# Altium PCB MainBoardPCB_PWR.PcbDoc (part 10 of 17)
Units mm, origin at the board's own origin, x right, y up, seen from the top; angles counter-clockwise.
Board outline 333.63 x 349.38 mm, 16 copper layers (L1, L2 (GND), L3 (Sign), L4 (GND), L5 (Sign), L6 (PWR/GND), L7(PWR/GND), L8 (PWR/GND), L9 (PWR/GND), L10 (PWR/GND), L11 (PWR/GND), L12 (Sign), L13 (GND), L14 (Sign), L15 (GND), L16), stack 2.503 mm thick; 2187 components, 1615 nets, 7987 pads, 1695 vias.
Unrouted connection lines stored in the file: 4757.
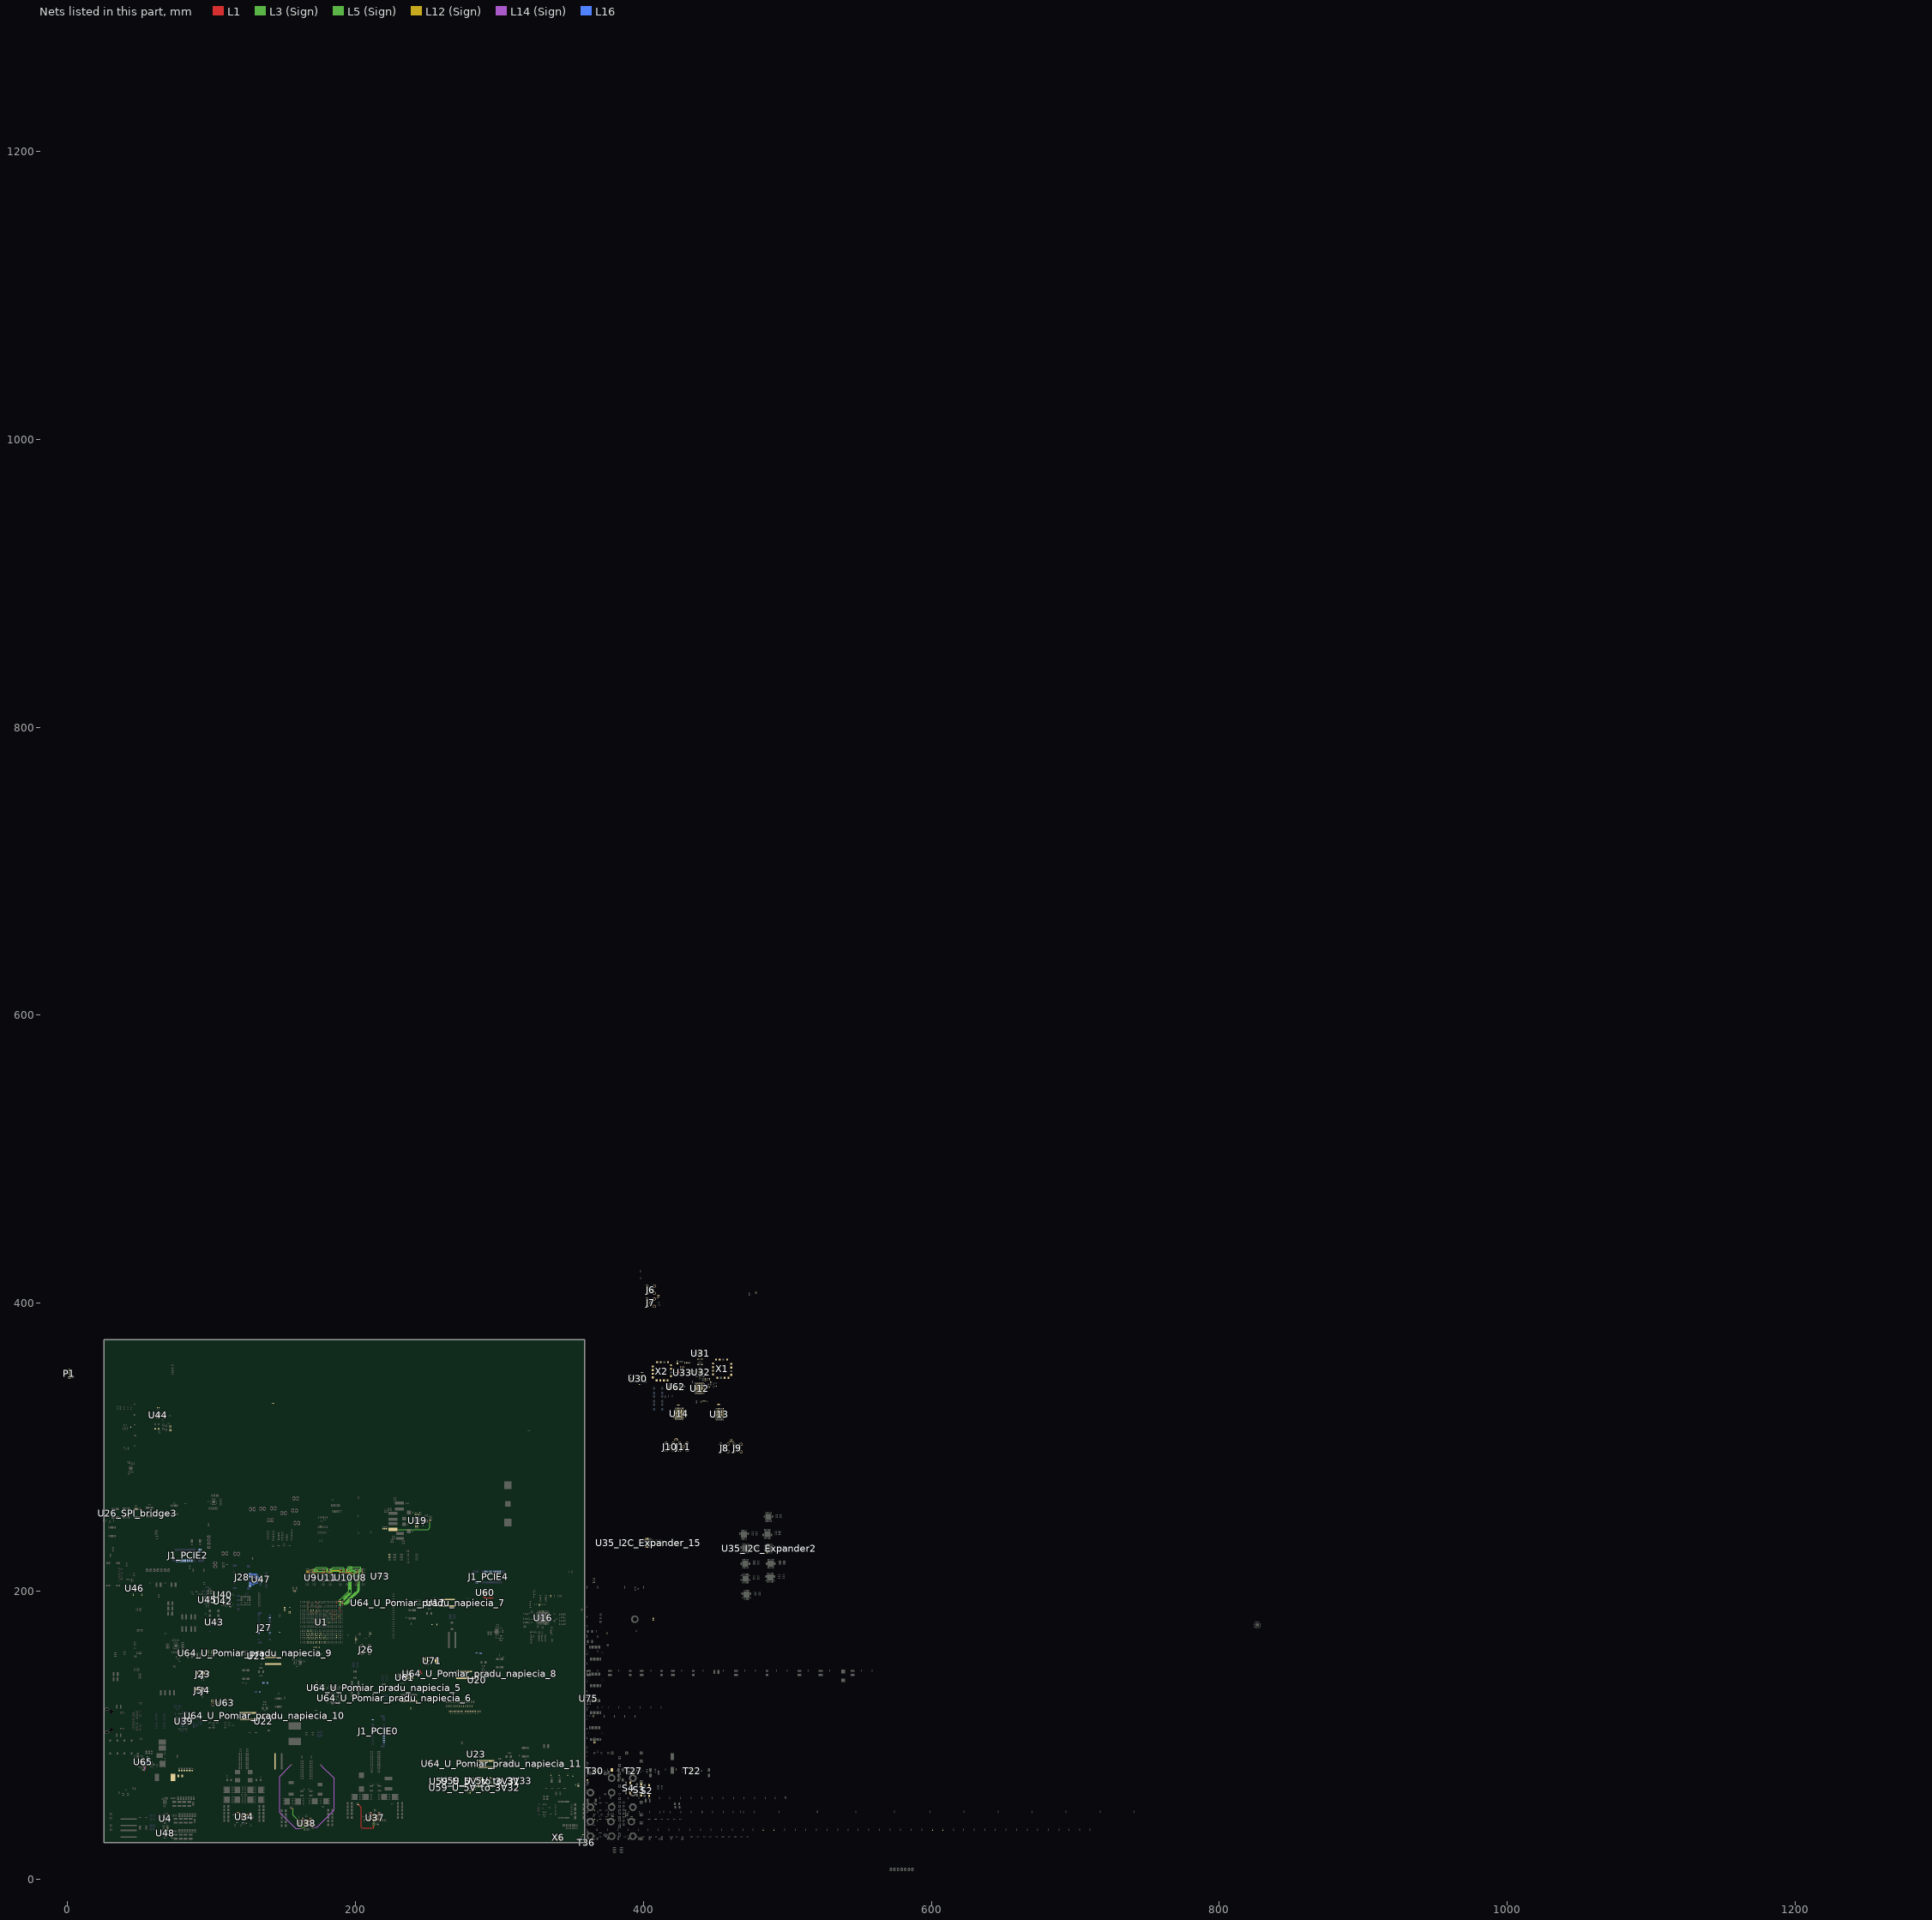
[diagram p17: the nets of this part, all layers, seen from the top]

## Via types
v1: diameter 0.5, hole 0.2, L1 to L16, 786 vias
v2: diameter 0.5/0.35/0.35/0.35/0.35/0.35/0.35/0.35/0.35/0.35/0.35/0.35/0.35/0.35/0.35/0.5 (per signal layer), hole 0.15, L1 to L16, tented both sides, 164 vias
v3: diameter 2.54, hole 1.02, L1 to L16, 152 vias
v4: diameter 0.5/0.35/0.35/0.35/0.35/0.35/0.35/0.35/0.35/0.35/0.35/0.35/0.35/0.35/0.35/0.5 (per signal layer), hole 0.2, L1 to L16, tented both sides, 100 vias
v5: diameter 0.45, hole 0.15, L1 to L16, 79 vias
v6: diameter 0.35/0/0.35 (per signal layer), hole 0.127, L1 to L3 (Sign), tented both sides, 78 vias
v7: diameter 0.45/0.45/0.45/0.45/0.45/0.45/0.45/0.45/0.45/0.45/0.45/0.45/0.45/0.45/0.45/0.45 (per signal layer), hole 0.15, L1 to L16, 65 vias
v8: diameter 0.4, hole 0.15, L1 to L16, 61 vias
v9: diameter 0.2, hole 0.1, L1 to L16, 35 vias
v10: diameter 0.5, hole 0.2, L1 to L16, tented both sides, 32 vias
v11: diameter 0.2/0/0.2 (per signal layer), hole 0.1, L1 to L3 (Sign), 28 vias
v12: diameter 0.4, hole 0.2, L1 to L16, 16 vias
v13: diameter 0.25, hole 0.2, L1 to L16, 16 vias
v14: diameter 0.3, hole 0.2, L1 to L16, 15 vias
v15: diameter 0.5/0.35/0.35/0.35/0.35/0.35/0.35/0.35/0.35/0.35/0.35/0.35/0.35/0.35/0.35/0.45 (per signal layer), hole 0.15, L1 to L16, tented both sides, 10 vias
v16: diameter 5, hole 3, L1 to L16, 9 vias
v17: diameter 0.2/0/0.2 (per signal layer), hole 0.1, L1 to L3 (Sign), tented both sides, 9 vias
v18: diameter 0.35/0/0.35 (per signal layer), hole 0.127, L1 to L3 (Sign), 7 vias
v19: diameter 0.35/0/0.35 (per signal layer), hole 0.127, L14 (Sign) to L16, tented both sides, 5 vias
v20: diameter 1.65, hole 1.65, L1 to L16, 4 vias
v21: diameter 1.15, hole 1.15, L1 to L16, 4 vias
v22: diameter 0.35, hole 0.127, L1 to L2 (GND), 2 vias
v23: diameter 0.4, hole 0.2, L1 to L16, tented both sides, 2 vias
v24: diameter 0.35, hole 0.127, L1 to L2 (GND), tented both sides, 2 vias
v25: diameter 0.508, hole 0.127, L1 to L2 (GND), 2 vias
v26: diameter 0.508, hole 0.127, L2 (GND) to L3 (Sign), 2 vias
v27: diameter 0.35, hole 0.127, L3 (Sign) to L6 (PWR/GND), tented both sides, 2 vias
v28: diameter 0.5, hole 0.2, L3 (Sign) to L6 (PWR/GND), tented both sides, 2 vias
v29: diameter 5.5, hole 3.5, L1 to L16, 1 vias
v30: diameter 0.45/0.45/0.45 (per signal layer), hole 0.15, L1 to L3 (Sign), 1 vias
v31: diameter 0.35/0.35/0.35 (per signal layer), hole 0.127, L1 to L3 (Sign), tented both sides, 1 vias
v32: diameter 0.45/0/0.45 (per signal layer), hole 0.15, L1 to L3 (Sign), tented both sides, 1 vias
v33: diameter 0.45/0/0.45 (per signal layer), hole 0.2, L14 (Sign) to L16, tented both sides, 1 vias
v34: diameter 0.35, hole 0.127, L2 (GND) to L3 (Sign), 1 vias

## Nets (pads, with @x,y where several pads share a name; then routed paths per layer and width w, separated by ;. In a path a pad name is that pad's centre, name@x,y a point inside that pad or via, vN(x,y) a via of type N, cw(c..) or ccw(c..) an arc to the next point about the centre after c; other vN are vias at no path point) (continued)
5V_RAIL: C515.2 C516.2 C563_U_5V_to_3V31.2 C563_U_5V_to_3V32.2 C563_U_5V_to_3V33.2 C564_U_5V_to_3V31.2 C564_U_5V_to_3V32.2 C564_U_5V_to_3V33.2 C574.2 C575.2 C720.2 C728.2 C733.2 D23.2 R315.2 R448_U_Pomiar_pradu_napiecia_6.2 R651.2 R656.2 T22.1 T27.2 T30.2 U40.1 U40.2 U40.3 U42.1 U42.2 U42.3 U45.21 U46.C3 U46.D3 U46.D4 U46.E3 U46.E4 U46.F3 U46.F4 U59_U_5V_to_3V31.1 U59_U_5V_to_3V31.2 U59_U_5V_to_3V32.1 U59_U_5V_to_3V32.2 U59_U_5V_to_3V33.1 U59_U_5V_to_3V33.2 U61.1 U61.2 U61.4 U61.5 U64_U_Pomiar_pradu_napiecia_6.8 U64_U_Pomiar_pradu_napiecia_6.9 U73.1 | length 54.5
  L14 (Sign) w0.254: v8(170.799,36.103) 173.242,36.103 185.2,48.06 ; v9(175.872,79.295) 185.204,69.963 185.204,48.06
12V_HiSpeed: C304.1 C305.1 C306.1 C307.1 C604.2 C714.2 FB34.1 L15.1 R448_U_Pomiar_pradu_napiecia_5.2 R626.2 U17.C3 U17.D3 U17.D4 U17.E3 U17.E4 U17.F3 U17.F4 U19.9 U19.11 U19.26 U19.28 U20.C3 U20.D3 U20.D4 U20.E3 U20.E4 U20.F3 U20.F4 U21.C3 U21.D3 U21.D4 U21.E3 U21.E4 U21.F3 U21.F4 U22.C3 U22.D3 U22.D4 U22.E3 U22.E4 U22.F3 U22.F4 U23.C3 U23.D3 U23.D4 U23.E3 U23.E4 U23.F3 U23.F4 U64_U_Pomiar_pradu_napiecia_5.8 U64_U_Pomiar_pradu_napiecia_5.9 U71.1 | length 58.1
  L1 w0.254: v8(161.537,35.058) R626.2@161.887,35.058 ; 245.476,144.878 245.476,143.28 245.982,142.773 245.982,142.723
  L14 (Sign) w0.254: v9(155.553,79.395) 147.38,71.222 147.38,46.175 158.497,35.058 v8(161.537,35.058)
12V_PCIE0: R448_U_Pomiar_pradu_napiecia_7.1 U17.C2 U17.D1 U17.D2 U17.E1 U17.E2 U17.F1 U17.F2 U64_U_Pomiar_pradu_napiecia_7.10
12V_PCIE0_CM: J1_PCIE0.60 J1_PCIE0.62 J1_PCIE0.64 J1_PCIE0.66 R448_U_Pomiar_pradu_napiecia_7.2 U64_U_Pomiar_pradu_napiecia_7.8 U64_U_Pomiar_pradu_napiecia_7.9
12V_PCIE1: R448_U_Pomiar_pradu_napiecia_8.1 U20.C2 U20.D1 U20.D2 U20.E1 U20.E2 U20.F1 U20.F2 U64_U_Pomiar_pradu_napiecia_8.10
12V_PCIE1_CM: R448_U_Pomiar_pradu_napiecia_8.2 U64_U_Pomiar_pradu_napiecia_8.8 U64_U_Pomiar_pradu_napiecia_8.9
12V_PCIE2: R448_U_Pomiar_pradu_napiecia_9.1 U21.C2 U21.D1 U21.D2 U21.E1 U21.E2 U21.F1 U21.F2 U64_U_Pomiar_pradu_napiecia_9.10
12V_PCIE2_CM: J1_PCIE2.60 J1_PCIE2.62 J1_PCIE2.64 J1_PCIE2.66 R448_U_Pomiar_pradu_napiecia_9.2 U64_U_Pomiar_pradu_napiecia_9.8 U64_U_Pomiar_pradu_napiecia_9.9
12V_PCIE3: R448_U_Pomiar_pradu_napiecia_10.1 U22.C2 U22.D1 U22.D2 U22.E1 U22.E2 U22.F1 U22.F2 U64_U_Pomiar_pradu_napiecia_10.10
12V_PCIE3_CM: R448_U_Pomiar_pradu_napiecia_10.2 U64_U_Pomiar_pradu_napiecia_10.8 U64_U_Pomiar_pradu_napiecia_10.9
12V_PCIE4: R448_U_Pomiar_pradu_napiecia_11.1 U23.C2 U23.D1 U23.D2 U23.E1 U23.E2 U23.F1 U23.F2 U64_U_Pomiar_pradu_napiecia_11.10
12V_PCIE4_CM: J1_PCIE4.60 J1_PCIE4.62 J1_PCIE4.64 J1_PCIE4.66 R448_U_Pomiar_pradu_napiecia_11.2 U64_U_Pomiar_pradu_napiecia_11.8 U64_U_Pomiar_pradu_napiecia_11.9
\I\N\T\: R709.2 U39.44
\M\R\: D11.1 D12.1 P5.1 R371.1 U44.13
ADP1741_3.6V: C308.2 C354.2 C355.2 C570.2 C603.2 L13.2 R113.2 U60.1 U60.2 U60.3 U60.15 U60.16 | length 31.4
  L1 w0.254: L13.2@225.965,242.859 229.313,242.859 229.431,242.741 v18(229.457,242.741) ; R113.2@251.788,249.011 251.788,248.318 251.811,248.295 v18(251.811,248.258)
  L3 (Sign) w0.254: v18(229.457,242.741) 250.449,242.741 251.811,244.104 v18(251.811,248.258)
ADP1741_EN: U35_I2C_Expander2.18 U60.4
ADP1741_PG: U35_I2C_Expander2.2 U60.5 | length 8.3
  L1 w0.254: U60.5@289.065,197.356 289.065,196.001 289.606,195.46 295.801,195.46
ADP_Vin_1: C395.2 R285.2 U37.3 | length 30.2
  L1 w0.254: R285.2@201.912,51.702 201.962,51.702 202.135,51.529 202.135,51.479 203.987,49.627 203.987,36.069 204.459,35.596 212.415,35.596 212.68,35.861 212.68,36.868 C395.2@212.81,36.998 v11(212.92,36.999) ; U37.3@212.795,40.359 212.795,39.955 v11(212.86,39.889)
  L3 (Sign) w0.254: v11(212.86,39.889) 212.92,39.83 v11(212.92,36.999)
ADP_Vin_2: C436.2 R303.2 U38.3 | length 19.4
  L1 w0.254: R303.2@155.628,49.178 v11(156.259,49.178) ; C436.2@160.318,38.813 v11(160.318,38.943) ; v11(165.283,36.265) U38.3@165.283,36.515
  L3 (Sign) w0.254: v11(156.259,49.178) 156.284,49.178 156.684,48.778 156.684,44.502 160.318,40.868 v11(160.318,38.943) 160.8,38.462 160.8,38.044 162.734,36.11 165.129,36.11 v11(165.283,36.265)
AGND: C45.1 C46.1 C55.1 C56.1 C57.1 C58.1 C59.1 C60.1 C61.1 C62.1 C65.1 C66.1 C68.1 C69.1 C71.1 C72.1 C73.1 C74.1 C84.1 C85.1 C86.1 C87.1 C94.1 C95.1 C97.1 C98.1 C111.1 C112.1 C113.1 C114.1 C115.1 C116.1 C117.1 C118.1 C119.1 C120.1 C121.1 C122.1 C123.1 C128.1 C129.1 C130.1 C131.1 C132.1 C133.1 C134.1 C135.1 C136.1 C137.1 C138.1 C139.1 C140.1 C149.1 C150.1 C151.1 C152.1 C153.1 C154.1 C155.1 C156.1 C157.1 C158.1 C159.1 C160.1 C161.1 C166.1 C167.1 C168.1 C169.1 C170.1 C171.1 C172.1 C173.1 C174.1 C175.1 C176.1 C177.1 C178.1 C181.1 C182.1 C183.1 C184.1 C185.1 C186.1 C187.1 C188.1 C189.1 C190.1 C191.1 C192.1 C193.1 C194.1 C195.1 C196.1 C197.1 C198.1 C199.1 C200.1 C201.1 C202.1 C203.1 C204.1 C205.1 C206.1 C322.1 C323.1 C324.1 C326.1 C327.1 C328.1 C329.1 C335.1 C336.1 C337.1 C338.1 C339.1 C340.1 C344.2 C563_U_5V_to_3V31.1 C563_U_5V_to_3V32.1 C563_U_5V_to_3V33.1 C564_U_5V_to_3V31.1 C564_U_5V_to_3V32.1 C564_U_5V_to_3V33.1 C565_U_5V_to_3V31.1 C565_U_5V_to_3V32.1 C565_U_5V_to_3V33.1 C566_U_5V_to_3V31.1 C566_U_5V_to_3V32.1 C566_U_5V_to_3V33.1 C567_U_5V_to_3V31.1 C567_U_5V_to_3V32.1 C567_U_5V_to_3V33.1 C568.1 C569.1 C570.1 C571.2 C580.1 C581.1 C582.1 C583.1 C584.1 C713.1 C714.1 FB35.2 J2.1 J2.3 J3.1 J3.3 J4.1 J4.3 J5.1 J5.3 J6.2 J6.3 J6.4 J6.5 J7.2 J7.3 J7.4 J7.5 J8.2 J8.3 J8.4 J8.5 J9.2 J9.3 J9.4 J9.5 J10.2 J10.3 J10.4 J10.5 J11.2 J11.3 J11.4 J11.5 J26.2 J26.3 J26.4 J26.5 R246.1 R247.1 R248.1 R249.2 R254.1 R255.1 R256.1 R258.2 R261.1 R262.1 R263.1 R264.1 R265.1 R291.2 R301.2 R387.1 R432_U_5V_to_3V31.1 R432_U_5V_to_3V32.1 R432_U_5V_to_3V33.1 R434.1 R444.1 R445.1 R482.2 R483.2 R487.1 R536.2 R537.1 R609.1 T36.2 U12.36 U12.41 U12.53 U13.36 U13.41 U13.53 U14.36 U14.41 U14.53 U31.1 U31.2 U31.17 U32.1 U32.17 U33.5 U33.6 U33.14 U33.17 U59_U_5V_to_3V31.4 U59_U_5V_to_3V31.9 U59_U_5V_to_3V32.4 U59_U_5V_to_3V32.9 U59_U_5V_to_3V33.4 U59_U_5V_to_3V33.9 U60.6 U60.17 U62.5 U62.8 U62.11 U71.2 X1.1 X1.3 X1.4 X1.5 X1.6 X1.7 X1.8 X1.9 X1.11 X1.12 X1.13 X1.15 X1.16 | length 10.2
  L1 w0.116: v4(182.44,184.44) 182.927,184.927 ; v10(183.44,182.44) 183.927,182.927 ; 184.44,180.44 184.927,180.927 ; v4(184.44,186.414) 184.927,185.927 ; v4(185.44,183.44) 185.927,183.927 ; v10(186.44,181.44) 186.927,181.927 ; v4(186.44,192.414) 186.927,191.927 ; v4(188.44,182.44) 188.927,182.927 ; 188.927,187.927 v4(189.414,188.414) ; v10(189.44,180.44) 189.927,180.927 ; 189.927,185.927 v4(190.414,186.414) ; 189.927,190.927 v4(190.414,190.44) ; 190.927,192.927 v4(191.414,193.414)
  L1 w0.254: U60.6@289.715,197.356 289.715,196.668 290.047,196.336 290.047,196.326 C571.2@290.07,196.303
  other v1: 282.254,63.034 283.254,63.034 282.254,64.034 283.254,64.034 282.497,67.484 283.497,67.484 290.431,67.809 291.431,67.809 282.497,68.484 283.497,68.484 290.431,68.809 291.431,68.809 289.49,198.481 290.59,198.481 289.49,199.582 290.59,199.582 450.58,320.088 451.68,320.088 452.78,320.088 453.88,320.088 454.98,320.088 422.513,320.338 423.613,320.338 424.713,320.338 425.813,320.338 426.913,320.338 450.58,321.188 451.68,321.188 452.78,321.188 453.88,321.188 454.98,321.188 422.513,321.438 423.613,321.438 424.713,321.438 425.813,321.438 426.913,321.438 450.58,322.288 451.68,322.288 452.78,322.288 453.88,322.288 454.98,322.288 422.513,322.538 423.613,322.538 424.713,322.538 425.813,322.538 426.913,322.538 450.58,323.388 451.68,323.388 452.78,323.388 453.88,323.388 454.98,323.388 422.513,323.638 423.613,323.638 424.713,323.638 425.813,323.638 426.913,323.638 450.58,324.488 451.68,324.488 452.78,324.488 453.88,324.488 454.98,324.488 422.513,324.738 423.613,324.738 424.713,324.738 425.813,324.738 426.913,324.738 450.58,325.588 451.68,325.588 452.78,325.588 453.88,325.588 454.98,325.588 422.513,325.838 423.613,325.838 424.713,325.838 425.813,325.838 426.913,325.838 436.668,338.092 437.768,338.092 438.868,338.092 439.968,338.092 441.068,338.092 436.668,339.192 437.768,339.192 438.868,339.192 439.968,339.192 441.068,339.192 436.668,340.292 437.768,340.292 438.868,340.292 439.968,340.292 441.068,340.292 421.949,341.08 422.711,341.08 436.668,341.392 437.768,341.392 438.868,341.392 439.968,341.392 441.068,341.392 421.949,341.842 422.711,341.842 436.668,342.492 437.768,342.492 438.868,342.492 439.968,342.492 441.068,342.492 421.949,342.604 422.711,342.604 436.668,343.592 437.768,343.592 438.868,343.592 439.968,343.592 441.068,343.592
  other v4: 168.927,182.927 178.927,182.927 180.927,183.927 167.927,184.927 168.927,184.927 169.927,184.927 170.927,184.927 171.927,184.927 172.927,184.927 177.927,184.927 167.927,185.927 173.927,185.927 179.927,185.927 166.927,186.927 167.927,186.927 169.927,186.927 171.927,186.927 173.927,186.927 176.927,186.927 166.927,187.927 173.927,187.927 166.927,188.927 168.927,188.927 170.927,188.927 172.927,188.927 173.927,188.927 175.927,188.927 166.927,189.927 167.927,189.927 169.927,189.927 173.927,189.927 177.927,189.927 166.927,190.927 167.927,190.927 169.927,190.927 171.927,190.927 173.927,190.927 166.927,191.927 168.927,191.927 170.927,191.927 172.927,191.927 173.927,191.927 176.927,191.927 166.927,192.927 168.927,192.927 170.927,192.927 172.927,192.927 173.927,192.927
  other v12: 426.527,351.311 427.477,351.311 426.527,352.261 427.477,352.261
AGND_1: C389.1 C393.1 C395.1 C398.1 C399.1 C639.1 C640.1 C641.1 C642.1 C643.1 C644.1 R290.1 R294.1 R300.1 U37.6 U37.33
  other v1: 212.945,41.059 214.145,41.059 211.995,42.009 212.945,42.009 214.145,42.009 215.095,42.009 211.995,43.209 212.945,43.209 214.145,43.209 215.095,43.209 212.945,44.159 214.145,44.159
  other v5: 211.905,36.998 215.795,37.716 212.295,38.101 214.259,39.727 207.935,41.139 219.162,41.194 206.788,41.314 209.061,41.359 218.07,41.359 220.17,41.34 208.941,42.36 217.945,42.359 205.776,43.462 208.951,45.299 218.055,45.314
AGND_2: C430.1 C434.1 C436.1 C439.1 C440.1 C548.1 C549.1 C647.1 C648.1 C650.1 C652.1 R312.1 R318.1 R627.1 U38.6 U38.33
  other v1: 165.433,37.215 166.633,37.215 164.483,38.165 165.433,38.165 166.633,38.165 167.583,38.165 164.483,39.365 165.433,39.365 166.633,39.365 167.583,39.365 165.433,40.315 166.633,40.315
  other v5: 167.448,34.037 170.674,35.175 162.014,36.005 171.666,37.79 160.268,37.9 170.624,37.89 161.469,38.015 170.624,38.803 161.453,39.015
Analog_In5: U1.AD14
Analog_In6: U1.AA14
Analog_In7: U1.AB14
ANGD: C345.1 C349.1 C351.1 C356.1 C357.1 C358.2 C634.1 C635.1 R273.1 U34.6 U34.33
  other v1: 124.277,37.96 121.487,38.325 122.127,41.606 123.327,41.606 118.596,41.923 127.919,42.524 121.177,42.556 122.127,42.556 123.327,42.556 124.277,42.556 121.177,43.756 122.127,43.756 123.327,43.756 124.277,43.756 127.934,44.139 117.646,44.404 116.442,44.623 122.127,44.706 123.327,44.706
B223_Rx0_N: J1_PCIE0.47 U1.W3
B223_Rx0_P: J1_PCIE0.49 U1.W4
B223_Rx1_N: J1_PCIE0.35 U1.V5
B223_Rx1_P: J1_PCIE0.37 U1.V6
B223_Rx2_N: U1.T5
B223_Rx2_P: U1.T6
B223_Rx3_N: U1.R3
B223_Rx3_P: U1.R4
B223_Tx0_to_C_N: C268.1 J1_PCIE0.41
B223_Tx0_to_C_P: C267.1 J1_PCIE0.43
B223_Tx0C_to_B_N: C268.2 U1.V1
B223_Tx0C_to_B_P: C267.2 U1.V2
B223_Tx1_to_C_N: C270.1 J1_PCIE0.29
B223_Tx1_to_C_P: C269.1 J1_PCIE0.31
B223_Tx1C_to_B_N: C270.2 U1.U3
B223_Tx1C_to_B_P: C269.2 U1.U4
B223_Tx2_to_C_N: C272.1
B223_Tx2_to_C_P: C271.1
B223_Tx2C_to_B_N: C272.2 U1.T1
B223_Tx2C_to_B_P: C271.2 U1.T2
B223_Tx3_to_C_N: C275.1
B223_Tx3_to_C_P: C274.1
B223_Tx3C_to_B_N: C275.2 U1.P1
B223_Tx3C_to_B_P: C274.2 U1.P2
B224_Rx0_N: J1_PCIE2.47 U1.P5
B224_Rx0_P: J1_PCIE2.49 U1.P6
B224_Rx1_N: J1_PCIE2.35 U1.M5
B224_Rx1_P: J1_PCIE2.37 U1.M6
B224_Rx2_N: U1.L3
B224_Rx2_P: U1.L4
B224_Rx3_N: U1.K5
B224_Rx3_P: U1.K6
B224_Tx0_to_C_N: C280.1 J1_PCIE2.41
B224_Tx0_to_C_P: C279.1 J1_PCIE2.43
B224_Tx0C_to_B_N: C280.2 U1.N3
B224_Tx0C_to_B_P: C279.2 U1.N4
B224_Tx1_to_C_N: C282.1 J1_PCIE2.29
B224_Tx1_to_C_P: C281.1 J1_PCIE2.31
B224_Tx1C_to_B_N: C282.2 U1.M1
B224_Tx1C_to_B_P: C281.2 U1.M2
B224_Tx2_to_C_N: C284.1
B224_Tx2_to_C_P: C283.1
B224_Tx2C_to_B_N: C284.2 U1.K1
B224_Tx2C_to_B_P: C283.2 U1.K2
B224_Tx3_to_C_N: C287.1
B224_Tx3_to_C_P: C286.1
B224_Tx3C_to_B_N: C287.2 U1.J3
B224_Tx3C_to_B_P: C286.2 U1.J4
B225_Rx0_N: J1_PCIE4.47 U1.H5
B225_Rx0_P: J1_PCIE4.49 U1.H6
B225_Rx1_N: J1_PCIE4.35 U1.G7
B225_Rx1_P: J1_PCIE4.37 U1.G8
B225_Rx2_N: J1_PCIE4.23 U1.F5
B225_Rx2_P: J1_PCIE4.25 U1.F6
B225_Rx3_N: J1_PCIE4.11 U1.E7
B225_Rx3_P: J1_PCIE4.13 U1.E8
B225_Tx0_to_C_N: C292.1 J1_PCIE4.41
B225_Tx0_to_C_P: C291.1 J1_PCIE4.43
B225_Tx0C_to_B_N: C292.2 U1.H1
B225_Tx0C_to_B_P: C291.2 U1.H2
B225_Tx1_to_C_N: C294.1 J1_PCIE4.29
B225_Tx1_to_C_P: C293.1 J1_PCIE4.31
B225_Tx1C_to_B_N: C294.2 U1.G3
B225_Tx1C_to_B_P: C293.2 U1.G4
B225_Tx2_to_C_N: C296.1 J1_PCIE4.19
B225_Tx2_to_C_P: C295.1 J1_PCIE4.17
B225_Tx2C_to_B_N: C296.2 U1.F1
B225_Tx2C_to_B_P: C295.2 U1.F2
B225_Tx3_to_C_N: C299.1 J1_PCIE4.7
B225_Tx3_to_C_P: C298.1 J1_PCIE4.5
B225_Tx3C_to_B_N: C299.2 U1.E3
B225_Tx3C_to_B_P: C298.2 U1.E4
B503_Ground: C531.2 C532.2 C533.2 C534.2 C535.1 C536.1 P5.2 R358.2 R359.2 R360.2 R361.2 R373.1 R720.2 S2.3 S2.4 S3.3 S3.4 S4.3 S4.4 U43.9 U43.10 U44.4 U44.5 U44.17 X6.2 | length 0.9
  L1 w0.2: C535.1@157.404,200.432 C536.1@158.344,200.432
  other v1: 62.4,321.691 63.5,321.691 62.4,322.791 63.5,322.791
  other v22: 157.874,200.432
  other v34: 157.874,200.432
Bank223_MGTREF0_C_N: C276.1 U1.R7
Bank223_MGTREF0_C_P: C273.1 U1.R8
Bank223_MGTREF1_C_N: C278.1 U1.N7
Bank223_MGTREF1_C_P: C277.1 U1.N8
Bank224_MGTREF0_C_N: C288.1 U1.L7
Bank224_MGTREF0_C_P: C285.1 U1.L8
Bank224_MGTREF1_C_N: C290.1 U1.J7
Bank224_MGTREF1_C_P: C289.1 U1.J8
Bank225_MGTREF0_C_N: C300.1 U1.H9
Bank225_MGTREF0_C_P: C297.1 U1.H10
Bank225_MGTREF1_C_N: C302.1 U1.F9
Bank225_MGTREF1_C_P: C301.1 U1.F10
Bank505_MGTRREF0_C_N: C526.2 R69.2 U1.M24
Bank505_MGTRREF0_C_P: C525.2 R69.1 U1.M23
Bank505_MGTRREF2_C_N: C528.2 R126.2 U1.K24
Bank505_MGTRREF2_C_P: C527.2 R126.1 U1.K23
Bank505_MGTRREF3_C_N: C530.2 R70.2 U1.H24
Bank505_MGTRREF3_C_P: C529.2 R70.1 U1.H23
Battery_PWR: P11.1 R679.2 R680.2 U48.2
  other v12: 68.417,32.112
BST1: C346.1 U34.25 | length 2.7
  L1 w0.254: C346.1@118.426,46.421 118.963,46.421 120.404,44.979 120.404,44.908 120.406,44.906 U34.25@120.477,44.906
BST1_1: C390.1 U37.25 | length 2.2
  L1 w0.254: C390.1@210.696,46.316 210.701,46.316 211.295,45.723 U37.25@211.295,44.359
BST1_2: C431.1 U38.25 | length 1.7
  L1 w0.254: C431.1@163.383,42.063 163.383,42.058 163.783,41.658 U38.25@163.783,40.515
BST2: C350.1 U34.16 | length 2.6
  L1 w0.254: U34.16@124.977,44.906 125.561,44.906 126.668,46.013 126.871,46.013 C350.1@127.014,46.156
BST2_1: C394.1 U37.16 | length 2.2
  L1 w0.254: U37.16@215.795,44.359 215.866,44.359 216.265,44.758 C394.1@216.265,46.316
BST2_2: C435.1 U38.16 | length 1.7
  L1 w0.254: U38.16@168.283,40.515 168.283,41.723 168.633,42.073 C435.1@168.633,42.078
CAN1_RxD: R798.1 U63.1
CAN1_TxD: R799.1 U63.4
CAN_H: P6.2 R446.2 R447.2 U63.7 U75.2
CAN_L: P6.1 R446.1 R447.1 U63.6 U75.1
CD_H: J28.9 R381.1 R782.1 U47.D3
Charge_CAP_KEY: R658.2
CLK_Fanout_In_N: U1.AF5
CLK_Fanout_In_P: U1.AF6
CLK_GTR_T1_N: C528.1
CLK_GTR_T1_P: C527.1
CLK_GTR_T2_N: C526.1
CLK_GTR_T2_P: C525.1
CLK_GTR_T3_N: C530.1
CLK_GTR_T3_P: C529.1
CLK_Hi_Rail1_N: R270.1 U12.33 U13.38
CLK_Hi_Rail1_P: R270.2 U12.34 U13.37
CLK_Hi_Rail1_SysRef_N: R534.1 U12.30 U13.48
CLK_Hi_Rail1_SysRef_P: R534.2 U12.31 U13.47
CLK_Hi_Rail2_N: R539.1 U12.6 U14.38
CLK_Hi_Rail2_P: R539.2 U12.7 U14.37
CLK_Hi_Rail2_SysRef_N: R535.1 U12.3 U14.48
CLK_Hi_Rail2_SysRef_P: R535.2 U12.4 U14.47
CLK_M_OSC_In: C333.1 R257.2 U33.2 | length 2.7
  L1 w0.116: C333.1@422.947,351.917 422.993,351.917 R257.2@423.951,351.917 424.963,351.917 425.082,352.036 U33.2@425.602,352.036
CLK_NVME_Conn_N: J27.53 U14.13
CLK_NVME_Conn_P: J27.55 U14.12
CLK_Q223_T1_N: C276.2
CLK_Q223_T1_P: C273.2
CLK_Q224_T1_N: C288.2
CLK_Q224_T1_P: C285.2
CLK_Q225_T1_N: C300.2
CLK_Q225_T1_P: C297.2
CLK_Q226_T1_N: U1.B9
CLK_Q226_T1_P: U1.B10
CLK_SMA0_C_N: C48.2 J6.1
CLK_SMA0_C_P: C47.2 J7.1
CLK_SMA0_N: C48.1 R78.1 U12.9
CLK_SMA0_P: C47.1 R78.2 U12.10
CLK_SMA1_C_N: C50.2 J8.1
CLK_SMA1_C_P: C49.2 J9.1
CLK_SMA1_N: C50.1 R79.1 U13.3
CLK_SMA1_P: C49.1 R79.2 U13.4
CLK_SMA2_C_N: C52.2 J10.1
CLK_SMA2_C_P: C51.2 J11.1
CLK_SMA2_N: C52.1 R80.1 U14.34
CLK_SMA2_P: C51.1 R80.2 U14.33
CLKREF_R: R375.1 X6.3
CLKREQ: J27.52
CMD_SD: J28.3 U47.D4 | length 8
  L14 (Sign) w0.098: v33(129.438,209.982) 130.867,208.553 132.556,208.553 132.956,208.153 133.441,208.153 v19(133.841,207.753)
  L16 w0.098: J28.3@126.749,209.981 v33(129.438,209.982)
COMP1_1: C642.2 R624.2 U37.30 | length 2.7
  L1 w0.254: R624.2@209.801,40.359 209.821,40.379 209.821,41.339 C642.2@209.841,41.359 209.846,41.359 210.346,41.859 U37.30@211.295,41.859
COMP1_2: C548.2 R687.2 U38.30 | length 2.5
  L1 w0.254: R687.2@162.228,37.015 162.238,37.025 162.238,38.005 C548.2@162.249,38.015 U38.30@163.783,38.015
COMP2_1: C641.2 R623.2 U37.11 | length 2.6
  L1 w0.254: U37.11@215.795,41.859 216.66,41.859 217.16,41.359 C641.2@217.165,41.359 217.185,41.339 217.185,40.324 R623.2@217.205,40.305
COMP2_2: C650.2 R631.2 U38.11 | length 2.4
  L1 w0.254: U38.11@168.283,38.015 168.933,38.015 169.058,37.89 C650.2@169.734,37.89 169.754,37.87 169.754,37.02 R631.2@169.774,37
CSN: C694.2 C695.2 C696.2 C697.2 C698.2 C699.2 C700.2 R17.2 R140.2 R150.2 R666.2 U4.2 U65.10 | length 12.3
  L1 w0.254: R150.2@52.782,75.895 53.425,75.895 54.172,76.642 v9(54.172,78.202) 53.355,79.019 53.332,79.042 U65.10@53.332,79.367 ; R17.2@69.643,44.693 69.686,44.65 v5(70.536,44.65)
  L16 w0.254: v9(54.172,78.202) 54.172,80.097 56.068,81.993 v9@56.068,84.026
  other v9: 56.025,84.026
  other v12: 68.21,42.35
CSP: L22.2 R666.1 U65.9 | length 4.5
  L1 w0.254: U65.9@52.832,79.367 52.832,78.847 v9(53.572,78.107)
  L16 w0.254: v9(53.572,75.202) v9(53.572,78.107)
CSU: P1.2 R783.1
CSU_Neg: P1.3 R109.2
CSU_Pos: P1.1 R106.2
D_05028_G0: R540.2 U1.AA15 U16.45
D_05028_G0_1: R540.1 U35_I2C_Expander_15.2
D_05028_G3: U16.40 U35_I2C_Expander_15.18
D_05028_G4: U16.41 U35_I2C_Expander_15.3
D_05028_G5: U16.12 U35_I2C_Expander_15.22
D_05028_G6: U16.13 U35_I2C_Expander_15.19
D_05028_S0: U16.55 U35_I2C_Expander_15.21
D_05028_S1: U16.56 U35_I2C_Expander_15.20
DAC1220_Vref: C320.2 R608.1 R609.2 U30.12
DAC_AGND: U30.4 U30.13 X2.1 X2.3 X2.4 X2.5 X2.6 X2.7 X2.8 X2.9 X2.11 X2.12 X2.13 X2.15 X2.16
DAC_OUT: C321.2 U30.11 X2.2
DAC_SPI_CLK: U26_SPI_bridge3.14 U30.16
DAC_SPI_MOSI: R481.1 U26_SPI_bridge3.12 U30.15
DAS/DSS#: J27.10
DATA0_SD: J28.7 U47.D5 | length 8
  L16 w0.098: J28.7@126.749,205.581 126.98,205.812 131.593,205.812 131.978,206.197 131.978,206.896 132.836,207.753 U47.D5@133.439,207.753
DATA1_SD: J28.8 U47.E5 | length 8.3
  L16 w0.098: J28.8@126.749,204.481 129.361,204.481 130.48,205.6 131.762,205.6 132.309,206.146 132.309,206.794 132.868,207.353 U47.E5@133.439,207.353
DATA2_SD: J28.1 U47.A5 | length 8.6
  L16 w0.098: J28.1@126.749,212.181 131.141,212.181 131.886,211.436 131.886,210.506 U47.A5@133.439,208.953
DATA3_SD: J28.2 R383.1 U47.B5 | length 8
  L16 w0.098: J28.2@126.749,211.081 126.756,211.074 R383.1@130.487,211.074 130.487,210.546 131.356,209.677 132.067,209.677 133.191,208.553 U47.B5@133.439,208.553
Data_2_RX_PCIE0_N: J1_PCIE0.23
Data_2_RX_PCIE0_P: J1_PCIE0.25
Data_2_RX_PCIE1_N: 
Data_2_RX_PCIE1_P: 
Data_2_RX_PCIE2_N: J1_PCIE2.23
Data_2_RX_PCIE2_P: J1_PCIE2.25
Data_2_RX_PCIE3_N: 
Data_2_RX_PCIE3_P: 
Data_2_TX_PCIE0_N: J1_PCIE0.19
Data_2_TX_PCIE0_P: J1_PCIE0.17
Data_2_TX_PCIE1_N: 
Data_2_TX_PCIE1_P: 
Data_2_TX_PCIE2_N: J1_PCIE2.19
Data_2_TX_PCIE2_P: J1_PCIE2.17
Data_2_TX_PCIE3_N: 
Data_2_TX_PCIE3_P: 
Data_3_RX_PCIE0_N: J1_PCIE0.11
Data_3_RX_PCIE0_P: J1_PCIE0.13
Data_3_RX_PCIE1_N: 
Data_3_RX_PCIE1_P: 
Data_3_RX_PCIE2_N: J1_PCIE2.11
Data_3_RX_PCIE2_P: J1_PCIE2.13
Data_3_RX_PCIE3_N: 
Data_3_RX_PCIE3_P: 
Data_3_TX_PCIE0_N: J1_PCIE0.7
Data_3_TX_PCIE0_P: J1_PCIE0.5
Data_3_TX_PCIE1_N: 
Data_3_TX_PCIE1_P: 
Data_3_TX_PCIE2_N: J1_PCIE2.7
Data_3_TX_PCIE2_P: J1_PCIE2.5
Data_3_TX_PCIE3_N: 
Data_3_TX_PCIE3_P: 
DDR4_A0: R31.1 U1.AH30 U8.P3 U9.P3 U10.P3 U11.P3 | length 91.4
  L1 w0.116: v2(170.002,214.252) U9.P3@170.406,213.848 ; v2(181.463,214.252) U11.P3@181.866,213.848 ; U1.AH30@188.927,192.927 v6(189.414,193.414) ; v1(192.923,214.252) U10.P3@193.327,213.848 ; v15(204.356,214.248) 204.388,214.248 U8.P3@204.787,213.848
  L5 (Sign) w0.092: v2(170.002,214.252) 170.533,214.252 170.95,214.668 171.801,214.668 172.524,215.392 179.954,215.392 181.095,214.252 v2(181.463,214.252) 182.058,214.252 182.475,214.668 183.261,214.668 183.985,215.392 191.415,215.392 192.555,214.252 v1(192.923,214.252) 193.454,214.252 193.871,214.668 194.721,214.668 195.445,215.392 195.58,215.392 ccw(c195.58,215.482) 195.669,215.482 195.669,215.832 cw(c195.759,215.832) 195.759,215.921 196.027,215.921 cw(c196.027,215.832) 196.117,215.832 196.117,215.392 196.117,215.287 ccw(c196.207,215.287) 196.207,215.198 196.475,215.198 ccw(c196.475,215.287) 196.565,215.287 196.565,215.392 196.565,215.832 cw(c196.654,215.832) 196.654,215.921 196.923,215.921 cw(c196.923,215.832) 197.013,215.832 197.013,215.392 197.013,215.287 ccw(c197.102,215.287) 197.102,215.198 197.371,215.198 ccw(c197.371,215.287) 197.46,215.287 197.46,215.392 197.46,215.832 cw(c197.55,215.832) 197.55,215.921 197.819,215.921 cw(c197.819,215.832) 197.908,215.832 197.908,215.392 197.908,215.287 ccw(c197.998,215.287) 197.998,215.198 198.266,215.198 ccw(c198.266,215.287) 198.356,215.287 198.356,215.302 cw(c198.446,215.302) 198.446,215.392 202.875,215.392 202.97,215.297 ccw(c203.034,215.36) 203.097,215.297 203.098,215.298 cw(c203.161,215.235) 203.225,215.298 203.415,215.108 cw(c203.351,215.045) 203.415,214.982 203.35,214.917 203.286,214.852 ccw(c203.349,214.789) 203.286,214.726 203.476,214.536 ccw(c203.539,214.599) 203.602,214.536 203.604,214.537 cw(c203.667,214.474) 203.73,214.537 203.946,214.322 204.02,214.248 v15(204.356,214.248) v15@204.392,214.248
  L3 (Sign) w0.092: v6(189.414,193.414) 189.575,193.575 189.949,193.575 190.04,193.484 190.04,193.233 190.309,192.965 190.309,192.823 190.037,192.552 189.76,192.552 189.564,192.748 189.294,192.748 189.093,192.547 189.093,192.269 189.347,192.015 189.347,191.998 189.57,191.775 189.57,191.481 189.27,191.181 189.27,190.998 189.268,190.997 189.268,190.92 189.267,190.918 189.267,190.721 189.093,190.547 189.093,190.281 189.281,190.093 189.618,190.093 189.821,190.297 189.821,190.534 190.169,190.881 190.729,190.881 191.365,191.517 193.257,191.517 202.603,200.863 202.603,200.962 ccw(c202.504,200.962) 202.504,201.062 201.92,201.062 cw(c201.92,201.161) 201.82,201.161 201.82,201.359 cw(c201.92,201.359) 201.92,201.459 202.603,201.459 202.657,201.459 ccw(c202.657,201.558) 202.756,201.558 202.756,201.756 ccw(c202.657,201.756) 202.657,201.856 202.603,201.856 201.92,201.856 cw(c201.92,201.955) 201.82,201.955 201.82,202.153 cw(c201.92,202.153) 201.92,202.253 202.603,202.253 202.657,202.253 ccw(c202.657,202.352) 202.756,202.352 202.756,202.55 ccw(c202.657,202.55) 202.657,202.65 202.603,202.65 202.467,202.65 cw(c202.467,202.749) 202.367,202.749 202.367,202.947 cw(c202.467,202.947) 202.467,203.047 202.603,203.047 202.657,203.047 ccw(c202.657,203.146) 202.756,203.146 202.756,203.344 ccw(c202.657,203.344) 202.657,203.444 202.603,203.444 202.465,203.444 cw(c202.465,203.543) 202.366,203.543 202.366,203.741 cw(c202.465,203.741) 202.465,203.841 202.603,203.841 202.657,203.841 ccw(c202.657,203.94) 202.756,203.94 202.756,204.138 ccw(c202.657,204.138) 202.657,204.238 202.603,204.238 201.92,204.238 cw(c201.92,204.337) 201.82,204.337 201.82,204.535 cw(c201.92,204.535) 201.92,204.635 202.603,204.635 202.657,204.635 ccw(c202.657,204.734) 202.756,204.734 202.756,204.932 ccw(c202.657,204.932) 202.657,205.032 202.603,205.032 202.461,205.032 cw(c202.461,205.131) 202.361,205.131 202.361,205.329 cw(c202.461,205.329) 202.461,205.429 202.603,205.429 202.657,205.429 ccw(c202.657,205.528) 202.756,205.528 202.756,205.726 ccw(c202.657,205.726) 202.657,205.826 202.673,205.826 cw(c202.673,205.895) 202.603,205.895 202.603,207.01 202.603,211.273 202.971,211.642 202.971,214.678 203.421,215.128 203.926,215.128 204.063,214.992 204.063,214.918 204.064,214.916 204.064,214.82 204.391,214.493 v15@204.391,214.252
DDR4_A1: R33.1 U1.AG30 U8.P4 U9.P4 U10.P4 U11.P4 | length 91.1
  L1 w0.116: U9.P4@167.206,213.848 167.602,214.245 v2(167.605,214.245) ; U11.P4@178.666,213.848 179.063,214.245 v2(179.065,214.245) ; U1.AG30@187.927,192.927 v6(188.414,193.414) ; U10.P4@190.127,213.848 190.523,214.245 v2(190.526,214.245) v2@190.484,214.203 ; v15(201.176,214.244) U8.P4@201.58,213.841
  L12 (Sign) w0.092: 165.856,214.245 166.253,213.848 166.886,213.848 167.241,214.203 167.563,214.203 v2(167.605,214.245) v2@167.841,214.245 ; v2@167.602,214.245 v2@167.841,214.245 ; v2@179.063,214.245 180.018,214.245 ; v15(201.176,214.244) 200.909,214.244 200.589,213.924 200,213.924 199.457,213.924 cw(c199.403,213.924) 199.403,213.869 199.063,213.869 cw(c199.063,213.924) 199.009,213.924 199.009,214.488 ccw(c198.919,214.488) 198.919,214.578 198.651,214.578 ccw(c198.651,214.488) 198.561,214.488 198.561,213.924 cw(c198.507,213.924) 198.507,213.869 198.167,213.869 cw(c198.167,213.924) 198.113,213.924 198.113,214.488 ccw(c198.024,214.488) 198.024,214.578 197.755,214.578 ccw(c197.755,214.488) 197.665,214.488 197.665,214.013 cw(c197.576,214.013) 197.576,213.924 197.442,213.924 196.362,213.924 195.638,214.648 194.551,214.648 194.417,214.648 ccw(c194.417,214.558) 194.327,214.558 194.327,214.529 cw(c194.238,214.529) 194.238,214.44 193.969,214.44 cw(c193.969,214.529) 193.88,214.529 193.88,214.558 ccw(c193.79,214.558) 193.79,214.648 193.332,214.648 191.166,214.648 190.762,214.245 v2(190.526,214.245) 190.484,214.203 190.162,214.203 189.865,213.906 189.116,213.906 188.468,214.554 183.334,214.554 183.245,214.643 180.416,214.643 180.018,214.245 ; v2@167.841,214.245 168.245,214.648 173.172,214.648 173.896,213.924 178.744,213.924 v2(179.065,214.245) 180.018,214.245
  L3 (Sign) w0.092: v6(188.414,193.414) 189.081,194.081 189.498,194.081 195.498,200.082 195.498,200.52 195.498,200.773 ccw(c195.399,200.773) 195.399,200.873 195.067,200.873 cw(c195.067,200.972) 194.968,200.972 194.968,201.17 cw(c195.067,201.17) 195.067,201.27 195.498,201.27 196.385,201.27 ccw(c196.385,201.369) 196.484,201.369 196.484,201.567 ccw(c196.385,201.567) 196.385,201.667 195.498,201.667 195.067,201.667 cw(c195.067,201.766) 194.968,201.766 194.968,201.964 cw(c195.067,201.964) 195.067,202.064 195.498,202.064 196.385,202.064 ccw(c196.385,202.163) 196.484,202.163 196.484,202.361 ccw(c196.385,202.361) 196.385,202.461 195.498,202.461 195.067,202.461 cw(c195.067,202.56) 194.968,202.56 194.968,202.758 cw(c195.067,202.758) 195.067,202.858 195.498,202.858 196.385,202.858 ccw(c196.385,202.957) 196.484,202.957 196.484,203.155 ccw(c196.385,203.155) 196.385,203.255 195.498,203.255 195.067,203.255 cw(c195.067,203.354) 194.968,203.354 194.968,203.552 cw(c195.067,203.552) 195.067,203.652 195.498,203.652 196.385,203.652 ccw(c196.385,203.751) 196.484,203.751 196.484,203.949 ccw(c196.385,203.949) 196.385,204.049 195.498,204.049 195.067,204.049 cw(c195.067,204.148) 194.968,204.148 194.968,204.346 cw(c195.067,204.346) 195.067,204.446 195.498,204.446 196.385,204.446 ccw(c196.385,204.545) 196.484,204.545 196.484,204.743 ccw(c196.385,204.743) 196.385,204.843 195.498,204.843 195.067,204.843 cw(c195.067,204.942) 194.968,204.942 194.968,205.14 cw(c195.067,205.14) 195.067,205.24 195.498,205.24 196.385,205.24 ccw(c196.385,205.339) 196.484,205.339 196.484,205.537 ccw(c196.385,205.537) 196.385,205.637 195.498,205.637 195.087,205.637 cw(c195.087,205.736) 194.988,205.736 194.988,205.934 cw(c195.087,205.934) 195.087,206.034 195.498,206.034 196.385,206.034 ccw(c196.385,206.133) 196.484,206.133 196.484,206.331 ccw(c196.385,206.331) 196.385,206.431 195.598,206.431 cw(c195.598,206.53) 195.498,206.53 195.498,206.629 195.498,206.868 196.136,207.505 196.136,209.821 200.132,213.817 200.477,213.817 200.619,213.958 200.623,213.958 200.909,214.244 v15(201.176,214.244)
DDR4_A2: R35.1 U1.AK29 U8.R3 U9.R3 U10.R3 U11.R3 | length 91.2
  L1 w0.116: v2(170.002,215.052) U9.R3@170.406,214.648 ; v2(181.463,215.052) U11.R3@181.866,214.648 ; v6(190.44,191.44) U1.AK29@190.927,191.927 ; v2(192.923,215.052) U10.R3@193.327,214.648 ; v15(204.384,215.052) U8.R3@204.787,214.648
  L5 (Sign) w0.092: v2(170.002,215.052) 170.431,215.052 170.835,215.456 171.742,215.456 172.793,216.507 179.627,216.507 181.082,215.052 v2(181.463,215.052) 181.963,215.052 182.367,215.456 183.202,215.456 184.253,216.507 191.087,216.507 192.542,215.052 v2(192.923,215.052) 193.352,215.052 193.756,215.456 194.663,215.456 194.907,215.7 194.907,216.865 194.983,216.941 195.021,216.941 195.156,216.941 ccw(c195.156,217.031) 195.245,217.031 195.245,217.132 cw(c195.335,217.132) 195.335,217.221 195.603,217.221 cw(c195.603,217.132) 195.693,217.132 195.693,216.941 195.693,216.908 ccw(c195.782,216.908) 195.782,216.818 196.051,216.818 ccw(c196.051,216.908) 196.141,216.908 196.141,216.941 196.141,217.132 cw(c196.23,217.132) 196.23,217.221 196.499,217.221 cw(c196.499,217.132) 196.588,217.132 196.588,216.941 196.588,216.751 ccw(c196.678,216.751) 196.678,216.662 196.947,216.662 ccw(c196.947,216.751) 197.036,216.751 197.036,216.941 197.036,217.132 cw(c197.126,217.132) 197.126,217.221 197.395,217.221 cw(c197.395,217.132) 197.484,217.132 197.484,216.941 197.484,216.751 ccw(c197.574,216.751) 197.574,216.662 197.842,216.662 ccw(c197.842,216.751) 197.932,216.751 197.932,216.852 cw(c198.021,216.852) 198.021,216.941 198.133,216.941 203.657,216.941 203.76,216.838 203.76,215.677 204.384,215.053 v15(204.384,215.052)
  L3 (Sign) w0.092: v6(190.44,191.44) 190.709,191.709 192.993,191.709 193.063,191.78 ccw(c192.993,191.85) 193.063,191.92 192.844,192.139 cw(c192.914,192.209) 192.844,192.279 192.984,192.42 cw(c193.054,192.35) 193.124,192.42 193.414,192.13 193.429,192.115 ccw(c193.499,192.186) 193.569,192.115 193.709,192.256 ccw(c193.639,192.326) 193.709,192.396 193.694,192.411 193.406,192.7 cw(c193.476,192.77) 193.406,192.84 193.546,192.981 cw(c193.616,192.91) 193.686,192.981 193.975,192.692 193.99,192.677 ccw(c194.06,192.747) 194.131,192.677 194.271,192.817 ccw(c194.201,192.887) 194.271,192.958 194.256,192.973 193.968,193.261 cw(c194.038,193.331) 193.968,193.401 194.108,193.541 cw(c194.178,193.471) 194.248,193.541 194.537,193.253 194.552,193.238 ccw(c194.622,193.308) 194.692,193.238 194.832,193.379 ccw(c194.762,193.449) 194.832,193.519 194.817,193.534 194.53,193.822 cw(c194.6,193.892) 194.53,193.962 194.67,194.102 cw(c194.74,194.032) 194.81,194.102 195.098,193.815 195.113,193.8 ccw(c195.183,193.87) 195.253,193.8 195.394,193.94 ccw(c195.324,194.01) 195.394,194.08 195.379,194.096 195.092,194.383 cw(c195.162,194.453) 195.092,194.523 195.232,194.663 cw(c195.302,194.593) 195.372,194.663 195.659,194.376 195.675,194.361 ccw(c195.745,194.431) 195.815,194.361 195.955,194.502 ccw(c195.885,194.572) 195.955,194.642 195.94,194.657 195.654,194.943 cw(c195.724,195.014) 195.654,195.084 195.794,195.224 cw(c195.864,195.154) 195.934,195.224 196.221,194.938 196.236,194.923 ccw(c196.306,194.993) 196.376,194.923 196.517,195.063 ccw(c196.446,195.133) 196.517,195.203 196.502,195.218 196.216,195.504 cw(c196.286,195.574) 196.216,195.645 196.356,195.785 cw(c196.426,195.715) 196.496,195.785 196.782,195.499 196.797,195.484 ccw(c196.868,195.554) 196.938,195.484 197.078,195.624 ccw(c197.008,195.695) 197.078,195.765 197.063,195.78 196.778,196.065 cw(c196.848,196.135) 196.778,196.206 196.918,196.346 cw(c196.988,196.276) 197.058,196.346 197.344,196.061 197.359,196.045 ccw(c197.429,196.116) 197.499,196.045 197.64,196.186 ccw(c197.569,196.256) 197.64,196.326 197.624,196.341 197.34,196.626 cw(c197.41,196.696) 197.34,196.766 197.48,196.907 cw(c197.55,196.837) 197.62,196.907 197.905,196.622 197.92,196.607 ccw(c197.99,196.677) 198.061,196.607 198.201,196.747 ccw(c198.131,196.817) 198.201,196.888 198.186,196.903 197.902,197.187 cw(c197.972,197.257) 197.902,197.327 198.042,197.468 cw(c198.112,197.397) 198.182,197.468 198.467,197.183 198.482,197.168 ccw(c198.552,197.239) 198.622,197.168 198.762,197.309 ccw(c198.692,197.379) 198.762,197.449 198.747,197.464 198.464,197.748 cw(c198.534,197.818) 198.464,197.888 198.604,198.029 cw(c198.674,197.958) 198.744,198.029 199.028,197.745 199.043,197.73 ccw(c199.113,197.8) 199.184,197.73 199.324,197.87 ccw(c199.254,197.94) 199.324,198.011 199.309,198.026 199.026,198.309 cw(c199.096,198.379) 199.026,198.449 199.166,198.589 cw(c199.236,198.519) 199.306,198.589 199.589,198.306 199.605,198.291 ccw(c199.675,198.361) 199.745,198.291 199.885,198.432 ccw(c199.815,198.502) 199.885,198.572 199.87,198.587 199.588,198.87 cw(c199.658,198.94) 199.588,199.01 199.728,199.15 cw(c199.798,199.08) 199.868,199.15 200.081,198.938 ccw(c200.151,199.008) 200.221,198.938 200.349,199.066 201.613,200.329 201.613,210.277 201.612,210.91 202.499,211.798 202.499,213.167 202.779,213.447 202.779,215.048 203.429,215.697 203.738,215.697 v15(204.384,215.052)
DDR4_A3: R37.1 U1.AJ30 U8.N4 U9.N4 U10.N4 U11.N4 | length 89.5
  L1 w0.116: U9.N4@167.206,213.048 167.602,213.445 v2(167.605,213.445) ; U11.N4@178.666,213.048 179.063,213.445 v2(179.065,213.445) ; U1.AJ30@189.927,192.927 v6(190.414,193.414) ; U10.N4@190.127,213.048 190.523,213.445 v2(190.526,213.445) ; U8.N4@201.587,213.048 201.984,213.445 v2(201.986,213.445)
  L12 (Sign) w0.092: 165.894,213.445 166.215,213.124 167.113,213.124 v2@167.426,213.436 ; v2(167.605,213.445) v2@167.426,213.436 ; v2@179.063,213.445 178.719,213.445 178.361,213.086 167.866,213.086 167.516,213.436 v2@167.426,213.436 ; v2(179.065,213.445) 180.09,213.445 180.48,213.055 183.553,213.055 184.34,213.843 188.112,213.843 188.831,213.124 190.034,213.124 190.347,213.436 190.436,213.436 190.787,213.086 193.357,213.086 193.841,213.086 cw(c193.841,212.997) 193.93,212.997 ; 193.93,212.996 ccw(c194.02,212.996) 194.02,212.906 194.289,212.906 ccw(c194.289,212.996) 194.378,212.996 ; 194.378,212.997 cw(c194.468,212.997) 194.468,213.086 194.602,213.086 194.653,213.086 194.989,212.75 195.123,212.75 ccw(c195.123,212.84) 195.212,212.84 195.212,212.913 cw(c195.302,212.913) 195.302,213.003 195.571,213.003 cw(c195.571,212.913) 195.66,212.913 195.66,212.75 195.66,212.576 ccw(c195.75,212.576) 195.75,212.487 196.019,212.487 ccw(c196.019,212.576) 196.108,212.576 196.108,212.75 196.108,212.913 cw(c196.198,212.913) 196.198,213.003 196.466,213.003 cw(c196.466,212.913) 196.556,212.913 196.556,212.75 196.556,212.576 ccw(c196.645,212.576) 196.645,212.487 196.914,212.487 ccw(c196.914,212.576) 197.004,212.576 197.004,212.661 cw(c197.093,212.661) 197.093,212.75 199.489,212.75 200.642,212.75 200.977,213.086 201.628,213.086 v2(201.986,213.445)
  L3 (Sign) w0.092: v6(190.414,193.414) 190.414,193.176 190.859,192.732 191.256,192.732 192.141,193.616 192.351,193.826 ccw(c192.281,193.897) 192.351,193.967 191.576,194.742 cw(c191.646,194.812) 191.576,194.882 191.716,195.023 cw(c191.787,194.952) 191.857,195.023 192.632,194.248 ccw(c192.702,194.318) 192.772,194.248 192.913,194.388 ccw(c192.842,194.458) 192.913,194.528 192.138,195.303 cw(c192.208,195.373) 192.138,195.444 192.278,195.584 cw(c192.348,195.514) 192.418,195.584 193.193,194.809 ccw(c193.263,194.879) 193.334,194.809 193.474,194.949 ccw(c193.404,195.02) 193.474,195.09 192.699,195.865 cw(c192.769,195.935) 192.699,196.005 192.839,196.145 cw(c192.91,196.075) 192.98,196.145 193.755,195.37 ccw(c193.825,195.441) 193.895,195.37 194.035,195.511 ccw(c193.965,195.581) 194.035,195.651 193.26,196.426 cw(c193.331,196.496) 193.26,196.566 193.401,196.707 cw(c193.471,196.637) 193.541,196.707 194.316,195.932 ccw(c194.386,196.002) 194.457,195.932 194.597,196.072 ccw(c194.527,196.142) 194.597,196.213 193.822,196.988 cw(c193.892,197.058) 193.822,197.128 193.962,197.268 cw(c194.032,197.198) 194.103,197.268 194.878,196.493 ccw(c194.948,196.563) 195.018,196.493 195.158,196.634 ccw(c195.088,196.704) 195.158,196.774 194.383,197.549 cw(c194.454,197.619) 194.383,197.689 194.524,197.83 cw(c194.594,197.76) 194.664,197.83 195.439,197.055 ccw(c195.509,197.125) 195.579,197.055 195.72,197.195 ccw(c195.65,197.265) 195.72,197.335 194.945,198.11 cw(c195.015,198.181) 194.945,198.251 195.085,198.391 cw(c195.155,198.321) 195.226,198.391 196,197.616 ccw(c196.071,197.686) 196.141,197.616 196.281,197.757 ccw(c196.211,197.827) 196.281,197.897 195.506,198.672 cw(c195.576,198.742) 195.506,198.812 195.647,198.953 cw(c195.717,198.882) 195.787,198.953 196.562,198.178 ccw(c196.632,198.248) 196.702,198.178 196.913,198.388 197.053,198.529 197.104,198.579 197.104,209.558 200.56,213.014 201.556,213.014 v2(201.986,213.445)
DDR4_A4: R39.1 U1.AK28 U8.N3 U9.N3 U10.N3 U11.N3 | length 88
  L1 w0.116: v2(170.002,213.452) U9.N3@170.406,213.048 ; v1(181.463,213.452) U11.N3@181.866,213.048 ; U1.AK28@190.927,190.927 v6(191.616,190.927) ; v2(192.923,213.452) U10.N3@193.327,213.048 ; v15(204.384,213.452) U8.N3@204.787,213.048
  L5 (Sign) w0.092: v2(170.002,213.452) 170.533,213.452 170.975,213.893 179.967,213.893 180.409,213.452 v1(181.463,213.452) 182.243,213.452 182.639,213.848 191.473,213.848 191.869,213.452 v2(192.923,213.452) 193.454,213.452 193.896,213.893 194.094,213.893 195.857,213.893 cw(c195.857,213.804) 195.947,213.804 195.947,213.735 ccw(c196.036,213.735) 196.036,213.646 196.305,213.646 ccw(c196.305,213.735) 196.394,213.735 196.394,213.893 196.394,214.208 cw(c196.484,214.208) 196.484,214.298 196.753,214.298 cw(c196.753,214.208) 196.842,214.208 196.842,213.983 ccw(c196.932,213.983) 196.932,213.893 197.2,213.893 ccw(c197.2,213.983) 197.29,213.983 197.29,214.208 cw(c197.38,214.208) 197.38,214.298 197.648,214.298 cw(c197.648,214.208) 197.738,214.208 197.738,213.983 ccw(c197.827,213.983) 197.827,213.893 198.096,213.893 ccw(c198.096,213.983) 198.186,213.983 198.186,214.208 cw(c198.275,214.208) 198.275,214.298 198.544,214.298 cw(c198.544,214.208) 198.633,214.208 198.633,213.983 ccw(c198.723,213.983) 198.723,213.893 198.992,213.893 ccw(c198.992,213.983) 199.081,213.983 199.081,214.208 cw(c199.171,214.208) 199.171,214.298 199.439,214.298 cw(c199.439,214.208) 199.529,214.208 199.529,213.983 ccw(c199.619,213.983) 199.619,213.893 199.977,213.893 200.335,213.893 cw(c200.335,213.804) 200.425,213.804 200.425,213.735 ccw(c200.514,213.735) 200.514,213.646 200.783,213.646 ccw(c200.783,213.735) 200.872,213.735 200.872,213.804 cw(c200.962,213.804) 200.962,213.893 201.231,213.893 cw(c201.231,213.804) 201.32,213.804 201.32,213.791 ccw(c201.41,213.791) 201.41,213.701 201.678,213.701 ccw(c201.678,213.791) 201.768,213.791 201.768,213.893 201.768,214.208 cw(c201.858,214.208) 201.858,214.298 202.126,214.298 cw(c202.126,214.208) 202.216,214.208 202.216,213.893 202.216,213.705 ccw(c202.305,213.705) 202.305,213.615 202.574,213.615 ccw(c202.574,213.705) 202.664,213.705 202.664,213.804 cw(c202.753,213.804) 202.753,213.893 202.888,213.893 203.329,213.452 v15(204.384,213.452)
  L3 (Sign) w0.092: v6(191.616,190.927) 191.847,190.927 191.946,190.927 ccw(c191.946,191.026) 192.046,191.026 cw(c192.145,191.026) 192.145,191.126 192.343,191.126 cw(c192.343,191.026) 192.443,191.026 192.443,190.927 192.443,190.787 ccw(c192.542,190.787) 192.542,190.688 192.74,190.688 ccw(c192.74,190.787) 192.84,190.787 192.84,190.828 cw(c192.939,190.828) 192.939,190.927 193.073,190.927 193.214,191.067 ; 193.213,191.068 cw(c193.283,191.138) 193.213,191.208 193.354,191.349 cw(c193.424,191.278) 193.494,191.349 ; 193.494,191.348 193.996,190.847 ccw(c194.066,190.917) 194.136,190.847 194.276,190.987 ccw(c194.206,191.057) 194.276,191.128 193.775,191.629 cw(c193.843,191.696) 193.775,191.764 193.921,191.91 cw(c193.988,191.842) 194.056,191.91 194.557,191.408 ccw(c194.627,191.478) 194.697,191.408 194.838,191.549 ccw(c194.768,191.619) 194.838,191.689 194.337,192.19 cw(c194.404,192.258) 194.337,192.325 194.482,192.471 cw(c194.55,192.404) 194.617,192.471 195.119,191.97 ccw(c195.189,192.04) 195.259,191.97 195.399,192.11 ccw(c195.329,192.18) 195.399,192.25 194.898,192.752 cw(c194.965,192.819) 194.898,192.887 195.044,193.032 cw(c195.111,192.965) 195.179,193.032 195.68,192.531 ccw(c195.75,192.601) 195.82,192.531 195.961,192.672 ccw(c195.891,192.742) 195.961,192.812 195.459,193.313 cw(c195.527,193.381) 195.459,193.448 195.605,193.594 cw(c195.673,193.526) 195.74,193.594 196.241,193.093 ccw(c196.312,193.163) 196.382,193.093 196.522,193.233 ccw(c196.452,193.303) 196.522,193.373 196.021,193.875 cw(c196.088,193.942) 196.021,194.01 196.167,194.155 cw(c196.234,194.088) 196.302,194.155 196.379,194.078 ccw(c196.449,194.149) 196.519,194.078 196.659,194.219 ccw(c196.589,194.289) 196.659,194.359 196.582,194.436 cw(c196.65,194.503) 196.582,194.571 196.728,194.717 cw(c196.796,194.649) 196.863,194.717 196.94,194.64 ccw(c197.01,194.71) 197.08,194.64 197.221,194.78 ccw(c197.151,194.85) 197.221,194.921 197.144,194.997 cw(c197.211,195.065) 197.144,195.132 197.29,195.278 cw(c197.357,195.211) 197.424,195.278 197.501,195.201 ccw(c197.572,195.271) 197.642,195.201 197.782,195.342 ccw(c197.712,195.412) 197.782,195.482 197.705,195.559 cw(c197.773,195.626) 197.705,195.694 197.851,195.84 cw(c197.918,195.772) 197.986,195.84 198.063,195.763 ccw(c198.133,195.833) 198.203,195.763 198.344,195.903 ccw(c198.273,195.973) 198.344,196.043 198.267,196.12 cw(c198.334,196.188) 198.267,196.255 198.412,196.401 cw(c198.48,196.334) 198.547,196.401 198.624,196.324 ccw(c198.694,196.394) 198.765,196.324 198.905,196.465 ccw(c198.835,196.535) 198.905,196.605 198.828,196.682 cw(c198.896,196.749) 198.828,196.817 198.974,196.963 cw(c199.041,196.895) 199.109,196.963 199.186,196.886 ccw(c199.256,196.956) 199.326,196.886 199.466,197.026 ccw(c199.396,197.096) 199.466,197.166 199.39,197.243 cw(c199.457,197.311) 199.39,197.378 199.535,197.524 cw(c199.603,197.457) 199.67,197.524 199.884,197.31 ccw(c199.954,197.38) 200.024,197.31 200.165,197.451 ccw(c200.095,197.521) 200.165,197.591 199.951,197.805 cw(c200.018,197.872) 199.951,197.94 200.097,198.085 cw(c200.164,198.018) 200.232,198.085 200.397,197.92 ccw(c200.468,197.99) 200.538,197.92 200.678,198.06 ccw(c200.608,198.13) 200.678,198.2 200.512,198.366 cw(c200.58,198.434) 200.512,198.501 200.658,198.647 cw(c200.726,198.579) 200.793,198.647 200.959,198.481 ccw(c201.029,198.551) 201.099,198.481 201.24,198.621 ccw(c201.169,198.692) 201.24,198.762 201.074,198.928 cw(c201.141,198.995) 201.074,199.062 201.22,199.208 cw(c201.287,199.141) 201.355,199.208 201.52,199.043 ccw(c201.591,199.113) 201.661,199.043 201.801,199.183 ccw(c201.731,199.253) 201.801,199.323 201.635,199.489 cw(c201.703,199.556) 201.635,199.624 201.781,199.77 cw(c201.849,199.702) 201.916,199.77 202.082,199.604 ccw(c202.152,199.674) 202.222,199.604 202.362,199.744 ccw(c202.292,199.815) 202.362,199.885 202.267,199.98 cw(c202.337,200.05) 202.267,200.121 202.457,200.311 202.964,200.818 202.964,211.363 203.237,211.635 203.237,213.536 203.517,213.817 204.172,213.817 204.384,213.606 v15(204.384,213.452)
